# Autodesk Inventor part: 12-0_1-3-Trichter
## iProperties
Created: 2006-01
Part Number: 12-0_1-3-Trichter
Document SubType Name: Blech
Designer: Armin Gräf
Stock Number: 12-0_1-3-Trichter
Author: Armin Gräf
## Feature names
1. Drehung1 [Revolution]
2. Grobblech1
3. Grobblech2
4. Biegung1
5. Grobblech3
6. Biegung2
7. Grobblech4
8. Biegung3
9. Grobblech5
10. Biegung4
11. Grobblech6
12. Biegung5
13. Grobblech7
14. Biegung6
15. Grobblech8
16. Biegung7
17. Grobblech9
18. Biegung8
19. Grobblech10
20. Biegung9
21. Grobblech11
22. Biegung10
23. Grobblech12
24. Biegung11
25. Grobblech13
26. Biegung12
27. Grobblech14
28. Biegung13
29. Grobblech15
30. Biegung14
31. Grobblech16
32. Biegung15
